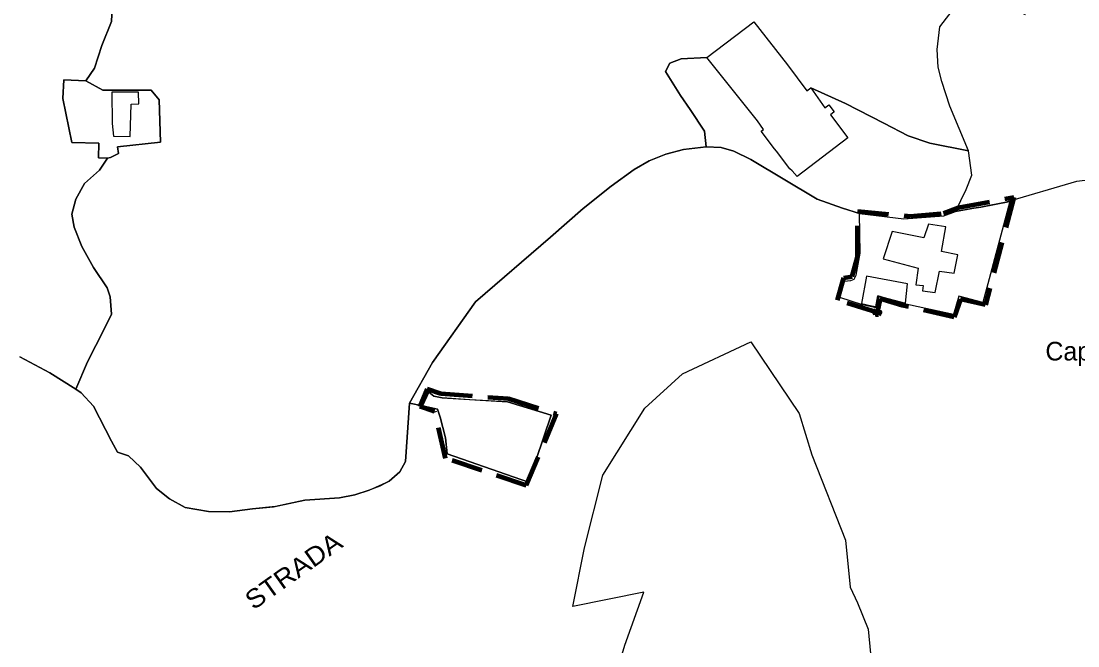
# Model space of a CAD drawing. Extents: x 652791 to 656927, y 889884 to 892405.
# Drawn here: x 655580 to 656147, y 891133 to 891468 of the extents above; entities that cross this region are included whole.
import ezdxf
from ezdxf.enums import TextEntityAlignment as Align

# ---------------------------------------------------------------- set-up
doc = ezdxf.new("R2010")
doc.units = 0
doc.header["$LTSCALE"] = 5.6
doc.header["$PDMODE"] = 32
doc.header["$PDSIZE"] = 2.8
doc.linetypes.add('MEDIUM_DASHED', pattern=[4.5, 3, -1.5])
for name, color, linetype, lineweight in [('1', 7, 'Continuous', 25), ('3', 7, 'Continuous', 25), ('35', 7, 'Continuous', 25), ('36', 7, 'Continuous', 25), ('37', 7, 'Continuous', 25), ('38', 7, 'Continuous', 25), ('7', 7, 'MEDIUM_DASHED', 100), ('9', 7, 'Continuous', 25)]:
    doc.layers.add(name, color=color, linetype=linetype, lineweight=lineweight)
doc.layers.add('60', color=7, linetype='Continuous')

msp = doc.modelspace()

# ---------------------------------------------------------------- linework, layer by layer
at = {"layer": '1'}
for points in [[(656030.07, 891364.83), (656030.07, 891364.83), (656053.81, 891361.98), (656075.35, 891363.51), (656081.59, 891365.81), (656091.47, 891367.73), (656095.2, 891368.25), (656110.65, 891371.26), (656096.25, 891317.09), (656083.35, 891320.35)], [(656025.35, 891328.76), (656027.21, 891329.63), (656028.2, 891331.74), (656030.42, 891343.51), (656030.07, 891364.83)], [(656083.35, 891320.35), (656080.48, 891310.57), (656053.24, 891316.44), (656040.31, 891320.04), (656039.04, 891314.08), (656031.74, 891315.79), (656019.56, 891319.7), (656021.84, 891328.41), (656025.35, 891328.76)]]:
    msp.add_lwpolyline(points, dxfattribs=at)
for points in [[(656047.54, 891355.11), (656042.82, 891340.46), (656061.62, 891335.43), (656060.31, 891326.5), (656064.2, 891326.2), (656063.89, 891323.36), (656070.66, 891322.42), (656073.03, 891333.88), (656080.89, 891332.82), (656082.83, 891342.69), (656074.12, 891344.32), (656076.36, 891357.65), (656067.07, 891358.99), (656064.52, 891351.73)], [(656033.8, 891331.14), (656031.13, 891316.41), (656038.81, 891314.63), (656039.97, 891320.62), (656054.66, 891316.73), (656055.83, 891327.09)]]:
    msp.add_lwpolyline(points, close=True, dxfattribs=at)
at = {"layer": '3'}
for points in [[(655602.74, 891426.47), (655607.46, 891402.8), (655622.09, 891402.57), (655621.86, 891394.56), (655626.69, 891394.4), (655628.32, 891394.85), (655632.49, 891396.98), (655632.03, 891400.59), (655655.02, 891403.03), (655654.47, 891425.7), (655650.12, 891430.96), (655624.14, 891431.04), (655614.99, 891436), (655603.19, 891436.45)], [(655629.07, 891429.96), (655629.15, 891413.04), (655629.98, 891406.28), (655638.79, 891406.16), (655639.38, 891423.45), (655643.55, 891423.56), (655643.3, 891429.96)]]:
    msp.add_lwpolyline(points, close=True, dxfattribs=at)
at = {"layer": '35'}
msp.add_line((655971.82, 891393.72), (656007.43, 891372.44), dxfattribs=at)
for points in [[(655582.42, 891644.49), (655582.09, 891638.7), (655583.7, 891632.26), (655594.96, 891616.49), (655603.32, 891604.9), (655612.65, 891590.41), (655619.73, 891574.32), (655622.62, 891560.8), (655622.3, 891547.92), (655618.76, 891538.59), (655616.83, 891525.71), (655618.76, 891511.87), (655621.98, 891502.86), (655624.88, 891490.95), (655629.38, 891478.72), (655628.74, 891467.78), (655623.59, 891454.9), (655619.73, 891442.67), (655614.99, 891436)], [(656078.47, 891422.3), (656074.29, 891435.57), (656072.29, 891443.27), (656071.65, 891452.77), (656073.24, 891465.01), (656081.57, 891475.88), (656089.03, 891484.77), (656071.19, 891488.48), (656054.45, 891495.4), (656041.28, 891499.66), (656031.95, 891504.45), (656049.79, 891536.92), (656026.15, 891549.44), (656015.9, 891559.7), (656007.97, 891578.31), (655999.02, 891581.54)], [(656422.77, 891464.02), (656413.94, 891456.5), (656226.36, 891386.67), (656205.54, 891383.87), (656165.13, 891384.18), (656146.48, 891382.01), (656108.81, 891370.86), (656095.2, 891368.25), (656091.47, 891367.73), (656081.59, 891365.81), (656087.34, 891377.65), (656090.3, 891385.37), (656088.48, 891398.33), (656078.47, 891422.3), (656074.29, 891435.57), (656072.29, 891443.27), (656071.65, 891452.77), (656073.24, 891465.01), (656081.57, 891475.88), (656089.03, 891484.77), (656095.78, 891483.3), (656118.99, 891471.57)], [(655626.69, 891394.4), (655621.86, 891394.56), (655622.09, 891402.57), (655607.46, 891402.8), (655602.74, 891426.47), (655603.19, 891436.45), (655614.99, 891436), (655619.73, 891442.67), (655623.59, 891454.9), (655628.74, 891467.78), (655629.38, 891478.72)], [(655947.74, 891400.48), (655946.98, 891408.99), (655939.23, 891420.62), (655934.07, 891428.05), (655926, 891440.98), (655928.26, 891445.5), (655934.39, 891447.76), (655948.23, 891448.48), (655973.43, 891467.57), (655991.42, 891444.51)], [(655948.23, 891448.48), (655934.39, 891447.76), (655928.26, 891445.5), (655926, 891440.98), (655934.07, 891428.05), (655939.23, 891420.62), (655946.98, 891408.99), (655947.74, 891400.48)], [(655948.23, 891448.48), (655934.39, 891447.76), (655928.26, 891445.5), (655926, 891440.98), (655934.07, 891428.05), (655939.23, 891420.62)], [(656043.19, 891413.19), (656022.53, 891423.85), (656004.03, 891432.15), (656011.54, 891421.4), (656013.65, 891423.03), (656016.53, 891419.26), (656014.51, 891417.68), (656023.82, 891405.38), (655996.54, 891384.72), (655993.99, 891387.65), (655992.62, 891388.74), (655985.51, 891398.14), (655984.51, 891399.47), (655977.33, 891408.97), (655978.58, 891409.88), (655975.35, 891414.49), (655948.23, 891448.48)], [(655991.42, 891444.51), (656001.81, 891430.58), (656004.03, 891432.15), (656022.53, 891423.85), (656043.19, 891413.19), (656056.11, 891406.41)], [(655614.99, 891436), (655624.14, 891431.04), (655650.12, 891430.96), (655654.47, 891425.7), (655655.02, 891403.03), (655632.03, 891400.59), (655632.49, 891396.98), (655628.32, 891394.85), (655626.69, 891394.4)], [(656004.03, 891432.15), (656022.53, 891423.85), (656043.19, 891413.19), (656056.11, 891406.41), (656067.73, 891402.53), (656088.48, 891398.33)], [(655939.23, 891420.62), (655946.98, 891408.99), (655947.74, 891400.48), (655955.78, 891400.14)], [(656056.11, 891406.41), (656067.73, 891402.53), (656088.48, 891398.33), (656078.47, 891422.3)], [(656088.48, 891398.33), (656067.73, 891402.53), (656056.11, 891406.41), (656043.19, 891413.19)], [(655926.2, 891396.68), (655935.57, 891399.18), (655947.74, 891400.48)], [(655955.78, 891400.14), (655962.62, 891398.23), (655971.82, 891393.72)], [(656081.59, 891365.81), (656087.34, 891377.65), (656090.3, 891385.37), (656088.48, 891398.33)], [(655609.62, 891270.6), (655615.87, 891285.26), (655624.88, 891302.65), (655628.74, 891310.69), (655628.09, 891320.03), (655626.49, 891324.85), (655619.09, 891335.8), (655612.98, 891347.06), (655608.79, 891357.37), (655607.51, 891364.45), (655609.76, 891372.5), (655614.26, 891380.87), (655622.3, 891387.95), (655626.69, 891394.4)], [(655626.69, 891394.4), (655622.3, 891387.95), (655614.26, 891380.87), (655609.76, 891372.5), (655607.51, 891364.45), (655608.79, 891357.37), (655612.98, 891347.06), (655619.09, 891335.8), (655626.49, 891324.85), (655628.09, 891320.03), (655628.74, 891310.69), (655624.88, 891302.65), (655615.87, 891285.26), (655609.62, 891270.6)], [(655896.94, 891379.46), (655909.15, 891388.41), (655917.16, 891393.03), (655926.2, 891396.68)], [(655777.72, 891221.15), (655783.44, 891226.13), (655786.45, 891231.66), (655788.66, 891263.09), (655801.05, 891284.78), (655824.05, 891317.31), (655864.3, 891352.06), (655881.89, 891367.38), (655896.94, 891379.46)], [(656007.43, 891372.44), (656021.02, 891367.61), (656030.07, 891364.83), (656053.81, 891361.98), (656075.35, 891363.51), (656081.59, 891365.81)], [(655579.68, 891287.83), (655595.82, 891279.36), (655609.62, 891270.6)], [(655609.62, 891270.6), (655612.5, 891268.62), (655619.19, 891261.38), (655628.81, 891242.58), (655632.11, 891236.8), (655637.97, 891234.79), (655644.3, 891228.65), (655652.91, 891217.19), (655659.96, 891211.61), (655668.3, 891207.03), (655680.94, 891204.83)], [(655759.41, 891213.88), (655767.1, 891216.28), (655777.72, 891221.15)], [(655680.94, 891204.83), (655692.21, 891204.64), (655704.46, 891206.35), (655715.79, 891207.43), (655732.6, 891210.97), (655751.18, 891212.3), (655759.41, 891213.88)]]:
    msp.add_lwpolyline(points, dxfattribs=at)
at = {"layer": '36'}
msp.add_lwpolyline([(655897.47, 891110.32), (655904.1, 891133.25), (655914.35, 891161.62), (655876.33, 891153.86), (655882.51, 891185.32), (655892.3, 891224.32), (655914.98, 891260.33), (655935.09, 891278.84), (655971.69, 891295.84), (655997.73, 891257.52), (656004.47, 891235.26), (656022.57, 891189.45), (656025.05, 891164.29), (656028.95, 891155.9), (656034.63, 891141.71), (656038.53, 891102.67)], dxfattribs=at)
at = {"layer": '37'}
msp.add_line((655788.66, 891263.09), (655786.45, 891231.66), dxfattribs=at)
for points in [[(655947.74, 891400.48), (655935.57, 891399.18), (655926.2, 891396.68)], [(655971.82, 891393.72), (655962.62, 891398.23), (655955.78, 891400.14), (655947.74, 891400.48)], [(655926.2, 891396.68), (655917.16, 891393.03), (655909.15, 891388.41), (655896.94, 891379.46), (655881.89, 891367.38), (655864.3, 891352.05), (655824.04, 891317.31), (655801.05, 891284.78), (655788.66, 891263.09)], [(656030.07, 891364.83), (656021.02, 891367.61), (656007.43, 891372.44), (655971.82, 891393.72)], [(656205.54, 891383.87), (656165.13, 891384.18), (656146.48, 891382), (656108.81, 891370.85), (656110.65, 891371.26), (656096.25, 891317.09), (656083.35, 891320.35), (656080.48, 891310.57), (656053.24, 891316.44), (656039.97, 891320.62), (656038.81, 891314.63), (656031.74, 891315.79), (656019.56, 891319.7), (656021.84, 891328.41), (656025.35, 891328.76)], [(656025.35, 891328.76), (656027.21, 891329.63), (656028.2, 891331.74), (656030.42, 891343.51), (656030.07, 891364.83)], [(655897.47, 891110.32), (655904.1, 891133.25), (655914.35, 891161.62), (655876.33, 891153.86), (655882.51, 891185.32), (655892.3, 891224.32), (655914.98, 891260.33), (655935.09, 891278.84), (655971.69, 891295.84), (655997.73, 891257.52), (656004.47, 891235.26), (656022.57, 891189.45), (656025.05, 891164.29), (656028.95, 891155.9), (656034.63, 891141.71), (656038.53, 891102.67)], [(655609.62, 891270.6), (655595.82, 891279.36), (655579.68, 891287.83)], [(655628.81, 891242.58), (655619.19, 891261.38), (655612.5, 891268.62), (655609.62, 891270.6)], [(655637.97, 891234.79), (655632.11, 891236.8), (655628.81, 891242.58)], [(655652.91, 891217.19), (655644.3, 891228.65), (655637.97, 891234.79)], [(655786.45, 891231.66), (655783.44, 891226.13), (655777.71, 891221.15)], [(655704.46, 891206.35), (655692.21, 891204.64), (655680.94, 891204.83), (655668.3, 891207.03), (655659.96, 891211.61), (655652.91, 891217.19)], [(655767.1, 891216.28), (655759.41, 891213.88), (655751.17, 891212.3), (655732.6, 891210.97), (655716.83, 891207.52), (655704.46, 891206.35)], [(655777.71, 891221.15), (655772.78, 891218.49), (655767.1, 891216.28)]]:
    msp.add_lwpolyline(points, dxfattribs=at)
msp.add_lwpolyline([(655788.66, 891263.09), (655795.69, 891261.6), (655798.99, 891268.87), (655801.68, 891266.83), (655806.17, 891265.96), (655841.22, 891263.75), (655864.61, 891256.59), (655852.58, 891220.65), (655808.89, 891235.87), (655807.95, 891244.39), (655805.12, 891255.5), (655803.7, 891259.85), (655795.69, 891261.6)], close=True, dxfattribs=at)
at = {"layer": '38'}
msp.add_lwpolyline([(655992.62, 891388.74), (655985.51, 891398.14), (655984.51, 891399.47), (655977.33, 891408.97), (655978.58, 891409.88), (655975.35, 891414.49), (655948.23, 891448.48), (655973.43, 891467.57), (655991.42, 891444.51), (656001.81, 891430.58), (656004.03, 891432.15), (656011.54, 891421.4), (656013.65, 891423.03), (656016.53, 891419.26), (656014.51, 891417.68), (656023.82, 891405.38), (655996.54, 891384.72), (655993.99, 891387.65)], close=True, dxfattribs=at)
at = {"layer": '7'}
for points in [[(656039.57, 891311.73), (656018.2, 891318.28), (656021.62, 891330.18), (656026.19, 891330.99), (656028.96, 891341.43), (656028.96, 891366.04), (656057.19, 891363.43), (656075.06, 891364.9), (656083.21, 891368), (656112.86, 891373.54), (656097.71, 891315.83), (656084.18, 891318.77)], [(656084.18, 891318.77), (656080.91, 891309.14), (656052.94, 891315.47), (656041.17, 891318.93), (656039.57, 891311.73)]]:
    msp.add_lwpolyline(points, dxfattribs=at)
msp.add_lwpolyline([(655798.13, 891270.79), (655805.56, 891268.13), (655841.87, 891265.48), (655867.58, 891257.26), (655851.33, 891218.78), (655807.94, 891233.39), (655802.11, 891258.59), (655794.16, 891261.24)], close=True, dxfattribs=at)
msp.add_point((656039.57, 891311.73), dxfattribs=at)
at = {"layer": '9'}
msp.add_lwpolyline([(655807.95, 891244.39), (655808.89, 891235.87), (655852.58, 891220.65), (655864.61, 891256.59), (655841.22, 891263.75), (655820.96, 891264.79), (655806.17, 891265.96), (655801.68, 891266.83), (655798.99, 891268.87), (655795.69, 891261.6), (655803.7, 891259.85), (655805.12, 891255.5)], close=True, dxfattribs=at)

# ---------------------------------------------------------------- texts
at = {"layer": '60'}
msp.add_text('Capugnano', height=10, dxfattribs=at).set_placement((656164.37, 891285.92), align=Align.CENTER)
at = {"layer": '60', "width": 1.1}
msp.add_text('STRADA', height=10, rotation=35.368, dxfattribs=at).set_placement((655729.34, 891169), align=Align.CENTER)

doc.saveas('drawing.dxf')
